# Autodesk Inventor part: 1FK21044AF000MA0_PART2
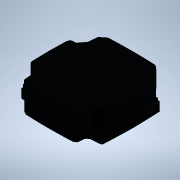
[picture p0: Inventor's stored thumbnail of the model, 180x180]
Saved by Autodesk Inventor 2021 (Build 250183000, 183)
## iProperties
Created: 2025-04
Part Number: 1FK21044AF000MA0_PART2
Material: Generic
Catalog Web Link: www.3dfindit.com
Description: -Servo synchronous motor
Document SubType Name: Modeling
Designer: psAdmin
Mass: 135.825 g
Surface Area: 188.795 cm^2
Volume: 135.825 cm^3
Density: 1 g/cm^3
Appearance: PSOLRGB-38-46-56
Category: PARTsolutions
Title: 1FK21044AF000MA0_PART2
Author: Cadenas PARTsolutions
Comments: Servo synchronous motor
Sending System: PARTsolutions
Preprocessor: ST-DEVELOPER v19.3
PSOL_IDENT_0: {$CADENAS_DATA/23d-libs/siemens_ag/_cat_/39/c4/1fk21044af000ma0.prj},213 {VTYP=3D},{NB=1FK21044AF000
PSOL_IDENT_1: MA0_PART2},{LINA=1FK21044AF000MA0_PART2},{NN=1FK21044AF000MA0_PART2},{NOPRJ=TRUE},{DATE=19.08.2025 1
PSOL_IDENT_2: 4:00:33},{GEOMDATE=30.07.2025 02:02:22},{VERSION=},{LINEID=10},{WBVAR=},{WBNUMERIC=}  {NB=1FK21044AF
PSOL_IDENT_3: 000MA0_PART2},{LINA=1FK21044AF000MA0_PART2},{KT=DUMMY},{PREVIEW=../../../_pool_/cb/72/p_d211_xx_0043
PSOL_IDENT_4: 4j.png},{DESCSHORT=SIMOTICS S-1FK2 HD, SINAMICS S210 3AC 400V-480V, 1.27 Nm, 3000 rpm},{DESCLONG=SIM
PSOL_IDENT_5: OTICS S-1FK2 HD servo motor M0=1.27 Nm; PN = 0.4 kW at nN=3000 rpm (380-480 V); PN = 0.2 kW at nN=15
PSOL_IDENT_6: 00 rpm (200-240 V); degree of protection IP64; cylindrical shaft D19x40mm; absolute encoder 22-bit +
PSOL_IDENT_7: 12-bit multiturn (encoder AM22DQC); with OCC interface; plug size M17, rotatable; SIMOTICS S-1FK2 s
PSOL_IDENT_8: ervomotorfor a wide range of uses in industrial environments. SIMOTICS S‑1FK2 servomotors are compac
PSOL_IDENT_9: t synchronous motors with a high dynamic performance that set themselves apart as a result of their
PSOL_IDENT_10: high power density, degree of protection and overload capability. The motors are available in two va
PSOL_IDENT_11: riants: as High Dynamic variant (highest dynamic performance as a result of the low intrinsic moment
PSOL_IDENT_12: of inertia for applications demanding a high dynamic performance with low moved masses) - and as Co
PSOL_IDENT_13: mpact variant (precise and stable closed-loop control for medium up to large moved masses as a resul
PSOL_IDENT_14: t of a medium intrinsic moment of inertia). SIMOTICSS‑1FK2 servomotors fully exploit their strengths
PSOL_IDENT_15: in a system with the SINAMICSS210 frequency converter and simple connection using the one cable con
PSOL_IDENT_16: nection (OCC). Advantages include the short control and positioning times, fast and precise correcti
PSOL_IDENT_17: on of disturbing quantities as well as stable control with a high dynamic performance. The servo mot
PSOL_IDENT_18: ors can be configured to address a wide range of requirements. For example with and without holding
PSOL_IDENT_19: brake, IP64 or IP65 degree of protection, singleturn or multiturn absolute encoders - to name just a
PSOL_IDENT_20: few. Further, the servomotors are available in different shaft heights extending from 20 to 100. A
PSOL_IDENT_21: shaft sealing ring is available to achieve an IP65 degree of protection and for subsequent mounting
PSOL_IDENT_22: at the motor or as spare part. SIMOTICS - the optimum motor for each and every motion control applic
PSOL_IDENT_23: ation.},{INTNO=804766906428},{SUPPLIERALTNO=1FK2104-4AF00-0MA0},{MANUID=1FK21044AF000MA0},{MANUNAME=
PSOL_IDENT_24: Siemens},{MANUTYPEDESC=Synchronous motor 1FK2-HD 1.27 NM},{AAU732=SIMOTICS},{AAO057=S-1FK2},{AAU734=
PSOL_IDENT_25: SIMOTICS S-1FK2 HD servo motor M0=1.27 Nm; PN = 0.4 kW at nN=3000 rpm (380-480 V); PN = 0.2 kW at nN=
PSOL_IDENT_26: 1500 rpm (200-240 V); degree of protection IP64; cylindrical shaft D19x40mm; absolute encoder 22-bit
PSOL_IDENT_27: + 12-bit multiturn (encoder AM22DQC); with OCC interface; plug size M17, rotatable;},{AAW338=Synchr
PSOL_IDENT_28: onous motor 1FK2-HD 1.27 NM},{AAO742=SIMOTICS},{AAO663=4042948693322},{NOCUPEROU=1},{PRICEQUANTITY=1
PSOL_IDENT_29: },{QUANTITYMIN=1},{QUANTITYINT=1},{CTN=85015100},{COO=DE},{AAO676=1FK2104-4AF00-0MA0},{AAO677=Siemen
PSOL_IDENT_30: s AG},{ORDERUNIT=C62},{CONTENTUNIT=C62}
NB: 1FK21044AF000MA0_PART2
NT: Servo synchronous motor
NBSYN: $MANUID._PART2
LINA: 1FK21044AF000MA0_PART2
CATALOG: SIEMENS
PREVIEW: ../../../_pool_/cb/72/p_d211_xx_00434j.png
DESCSHORT: SIMOTICS S-1FK2 HD, SINAMICS S210 3AC 400V-480V, 1.27 Nm, 3000 rpm
DESCLONG: SIMOTICS S-1FK2 HD servo motor M0=1.27 Nm; PN = 0.4 kW at nN=3000 rpm (380-480 V); PN = 0.2 kW at nN=1500 rpm (200-240 V); degree of protection IP64; cylindrica
INTNO: 804766906428
SUPPLIERALTNO: 1FK2104-4AF00-0MA0
MANUID: 1FK21044AF000MA0
MANUNAME: Siemens
MANUTYPEDESC: Synchronous motor 1FK2-HD 1.27 NM
AAU732: SIMOTICS
AAO057: S-1FK2
AAU734: SIMOTICS S-1FK2 HD servo motor M0=1.27 Nm; PN = 0.4 kW at nN=3000 rpm (380-480 V); PN = 0.2 kW at nN=1500 rpm (200-240 V); degree of protection IP64; cylindrica
AAW338: Synchronous motor 1FK2-HD 1.27 NM
AAO742: SIMOTICS
AAO663: 4042948693322.0
NOCUPEROU: 1
PRICEQUANTITY: 1
QUANTITYMIN: 1
QUANTITYINT: 1
CTN: 85015100
COO: DE
ARTICLENO: 1FK21044AF000MA0_PART2
BOMINFO: 1FK21044AF000MA0_PART2
CREATOR: CADENAS GmbH
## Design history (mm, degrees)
feature "2025_04_17_15_01_27_0913"
body "Solid1"
